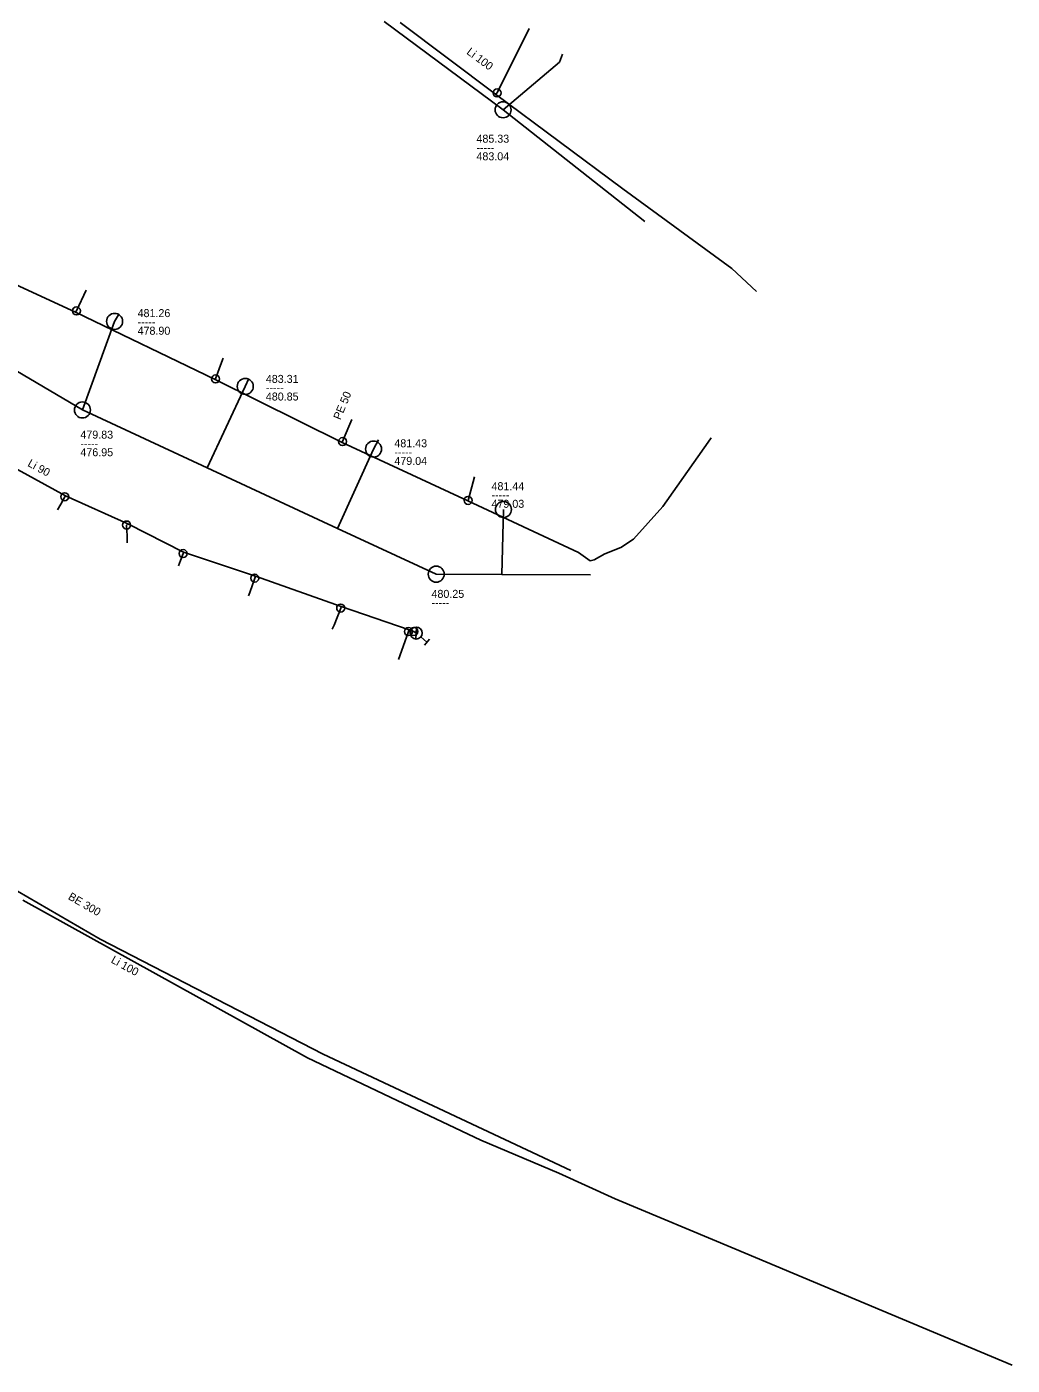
# Model space of a CAD drawing. Extents: x -685576 to -685145, y -1163436 to -1162895.
# Drawn here: x -685267.9 to -685144.7, y -1163436.2 to -1163269 of the extents above; entities that cross this region are included whole.
import ezdxf

# ---------------------------------------------------------------- set-up
doc = ezdxf.new("R2010")
doc.units = 0
doc.layers.add('Level 0', color=7, linetype='Continuous')

msp = doc.modelspace()

# ---------------------------------------------------------------- linework, layer by layer
at = {"layer": 'Level 0'}
for p, q in [((-685223.18, -1163268.34), (-685208.33, -1163279.35)), ((-685221.2, -1163268.46), (-685209.27, -1163277.38)), ((-685209.09, -1163277.25), (-685205.09, -1163269.2)), ((-685201.28, -1163273.41), (-685208.33, -1163279.35)), ((-685200.91, -1163272.42), (-685201.28, -1163273.41)), ((-685209.27, -1163277.38), (-685209.09, -1163277.25)), ((-685209.27, -1163277.38), (-685193.38, -1163289.21)), ((-685208.33, -1163279.35), (-685190.61, -1163293.29)), ((-685193.38, -1163289.21), (-685179.74, -1163299.19)), ((-685179.74, -1163299.19), (-685176.66, -1163302.07)), ((-685269.25, -1163301.17), (-685261.75, -1163304.63)), ((-685261.65, -1163304.47), (-685260.44, -1163301.89)), ((-685261.75, -1163304.63), (-685261.65, -1163304.47)), ((-685261.75, -1163304.63), (-685244.32, -1163313.06)), ((-685256.41, -1163304.96), (-685256.88, -1163305.78)), ((-685260.91, -1163316.85), (-685277.28, -1163307.23)), ((-685256.88, -1163305.78), (-685260.91, -1163316.85)), ((-685243.51, -1163310.92), (-685243.32, -1163310.37)), ((-685244.27, -1163312.97), (-685243.54, -1163310.94)), ((-685240.55, -1163313.91), (-685245.3, -1163324.09)), ((-685244.32, -1163313.06), (-685244.27, -1163312.97)), ((-685244.32, -1163313.06), (-685228.44, -1163320.9)), ((-685240.12, -1163312.91), (-685240.55, -1163313.91)), ((-685245.3, -1163324.09), (-685260.91, -1163316.85)), ((-685228.4, -1163320.79), (-685227.62, -1163318.92)), ((-685227.62, -1163318.92), (-685227.24, -1163318.05)), ((-685223.91, -1163320.59), (-685224.52, -1163321.73)), ((-685182.7, -1163320.88), (-685182.32, -1163320.35)), ((-685273.62, -1163321.79), (-685263.03, -1163327.59)), ((-685224.52, -1163321.73), (-685229.03, -1163331.64)), ((-685228.44, -1163320.9), (-685228.4, -1163320.79)), ((-685228.44, -1163320.9), (-685212.74, -1163328.21)), ((-685188.37, -1163328.92), (-685182.7, -1163320.88)), ((-685229.03, -1163331.64), (-685245.3, -1163324.09)), ((-685212.7, -1163328.15), (-685211.89, -1163325.22)), ((-685263.59, -1163328.6), (-685264.01, -1163329.32)), ((-685263.12, -1163327.69), (-685263.59, -1163328.6)), ((-685263.03, -1163327.59), (-685263.12, -1163327.69)), ((-685263.03, -1163327.59), (-685255.22, -1163331.08)), ((-685212.74, -1163328.21), (-685212.7, -1163328.15)), ((-685212.74, -1163328.2), (-685212.74, -1163328.21)), ((-685212.74, -1163328.21), (-685198.9, -1163334.66)), ((-685192.02, -1163332.97), (-685188.37, -1163328.92)), ((-685208.29, -1163329.28), (-685208.47, -1163337.39)), ((-685255.22, -1163331.08), (-685255.38, -1163331.22)), ((-685255.38, -1163331.22), (-685255.3, -1163332.58)), ((-685255.22, -1163331.08), (-685248.27, -1163334.61)), ((-685216.69, -1163337.36), (-685229.03, -1163331.64)), ((-685255.3, -1163332.58), (-685255.3, -1163333.44)), ((-685195.62, -1163334.81), (-685193.6, -1163334.04)), ((-685193.6, -1163334.04), (-685192.02, -1163332.97)), ((-685248.63, -1163335.64), (-685248.89, -1163336.32)), ((-685248.32, -1163334.78), (-685248.63, -1163335.64)), ((-685248.27, -1163334.61), (-685248.32, -1163334.78)), ((-685248.27, -1163334.61), (-685239.27, -1163337.62)), ((-685198.9, -1163334.66), (-685197.44, -1163335.7)), ((-685197.44, -1163335.7), (-685196.95, -1163335.55)), ((-685196.95, -1163335.55), (-685195.62, -1163334.81)), ((-685208.47, -1163337.39), (-685216.69, -1163337.36)), ((-685197.39, -1163337.43), (-685208.47, -1163337.39)), ((-685239.36, -1163337.86), (-685239.97, -1163339.64)), ((-685239.27, -1163337.62), (-685239.36, -1163337.86)), ((-685239.27, -1163337.62), (-685228.56, -1163341.41)), ((-685239.97, -1163339.64), (-685240.14, -1163340.08)), ((-685228.63, -1163341.59), (-685229.46, -1163343.72)), ((-685228.56, -1163341.41), (-685228.63, -1163341.59)), ((-685228.56, -1163341.41), (-685220.09, -1163344.32)), ((-685229.46, -1163343.72), (-685229.71, -1163344.25)), ((-685219.17, -1163343.97), (-685219.22, -1163345.47)), ((-685220.16, -1163344.53), (-685221.23, -1163347.57)), ((-685220.09, -1163344.32), (-685220.16, -1163344.53)), ((-685220.09, -1163344.32), (-685219.48, -1163344.52)), ((-685219.48, -1163344.52), (-685219.19, -1163344.72)), ((-685218.62, -1163345.2), (-685217.85, -1163345.84)), ((-685217.53, -1163345.46), (-685218.17, -1163346.23)), ((-685221.23, -1163347.57), (-685221.39, -1163348.04)), ((-685258.67, -1163382.95), (-685305.9, -1163355.68)), ((-685268.35, -1163378.09), (-685232.79, -1163397.77)), ((-685230.8, -1163397.31), (-685258.67, -1163382.95)), ((-685199.88, -1163411.84), (-685230.8, -1163397.31)), ((-685232.79, -1163397.77), (-685221.59, -1163403.11)), ((-685221.59, -1163403.11), (-685211.13, -1163408.07)), ((-685211.13, -1163408.07), (-685201.35, -1163412.2)), ((-685201.35, -1163412.2), (-685194.34, -1163415.4)), ((-685194.34, -1163415.4), (-685179.38, -1163421.64)), ((-685179.38, -1163421.64), (-685144.7, -1163436.18))]:
    msp.add_line(p, q, dxfattribs=at)
for centre, radius in [((-685209.09, -1163277.25), 0.5), ((-685208.33, -1163279.35), 1), ((-685261.65, -1163304.47), 0.5), ((-685256.88, -1163305.78), 1), ((-685244.27, -1163312.97), 0.5), ((-685240.55, -1163313.91), 1), ((-685260.91, -1163316.85), 1), ((-685228.4, -1163320.79), 0.5), ((-685224.52, -1163321.73), 1), ((-685263.12, -1163327.69), 0.5), ((-685212.7, -1163328.15), 0.5), ((-685208.29, -1163329.28), 1), ((-685255.38, -1163331.22), 0.5), ((-685248.32, -1163334.78), 0.5), ((-685239.36, -1163337.86), 0.5), ((-685216.69, -1163337.36), 1), ((-685228.63, -1163341.59), 0.5), ((-685220.16, -1163344.53), 0.5), ((-685219.48, -1163344.52), 0.5), ((-685219.19, -1163344.72), 0.75)]:
    msp.add_circle(centre, radius, dxfattribs=at)

# ---------------------------------------------------------------- texts
for s, rotation, p in [('Li 100', 323.333, (-685212.98, -1163272.3)), ('PE 50', 67.358, (-685228.67, -1163318.16)), ('Li 90', 331.291, (-685267.84, -1163323.81)), ('BE 300', 330.004, (-685262.78, -1163377.92)), ('Li 100', 331.039, (-685257.42, -1163385.83))]:
    msp.add_text(s, height=1, rotation=rotation, dxfattribs=at).set_placement(p)
for s, p in [('485.33', (-685211.66, -1163283.46)), ('483.04', (-685211.66, -1163285.66)), ('-----', (-685211.66, -1163284.56)), ('481.26', (-685254.01, -1163305.25)), ('478.90', (-685254.01, -1163307.45)), ('-----', (-685254.01, -1163306.35)), ('483.31', (-685237.98, -1163313.47)), ('480.85', (-685237.98, -1163315.67)), ('-----', (-685237.98, -1163314.57)), ('479.83', (-685261.16, -1163320.43)), ('481.43', (-685221.92, -1163321.51)), ('476.95', (-685261.16, -1163322.63)), ('-----', (-685261.16, -1163321.53)), ('-----', (-685221.92, -1163322.61)), ('479.04', (-685221.92, -1163323.71)), ('481.44', (-685209.78, -1163326.87)), ('479.03', (-685209.78, -1163329.07)), ('-----', (-685209.78, -1163327.97)), ('480.25', (-685217.28, -1163340.32)), ('-----', (-685217.28, -1163341.42))]:
    msp.add_text(s, height=1, dxfattribs=at).set_placement(p)

doc.saveas('drawing.dxf')
